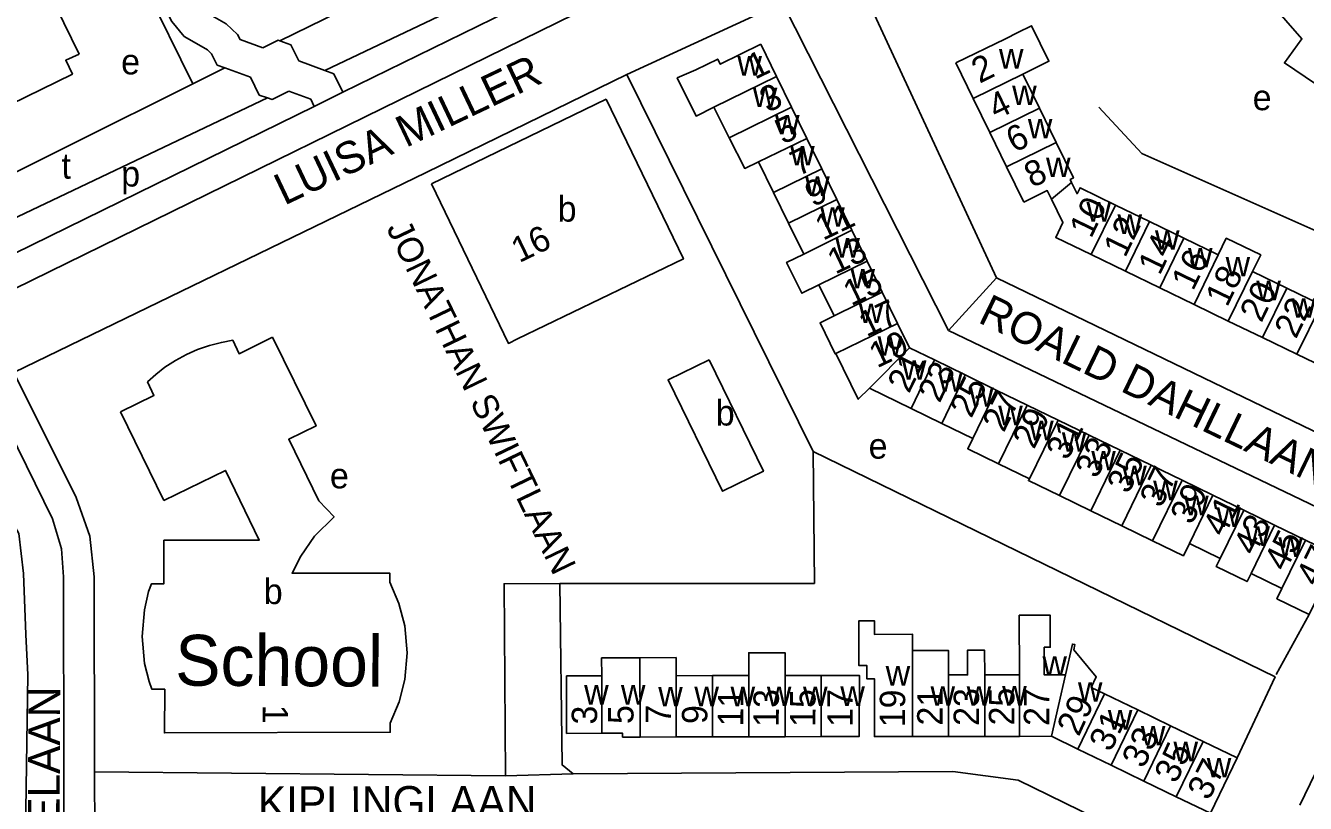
# Model space of a CAD drawing. Extents: x 159441 to 162086, y 388175 to 389787.
# Drawn here: x 161032.2 to 161233.6, y 388694.6 to 388817 of the extents above; entities that cross this region are included whole.
import ezdxf

# ---------------------------------------------------------------- set-up
doc = ezdxf.new("R2010")
doc.units = 0
for name, color, linetype in [('BLT_Basislijn', 7, 'Continuous'), ('BLT_Bebouwing', 7, 'Continuous'), ('BLT_Bebouwing_beschrifting', 7, 'Continuous'), ('BLT_Centroide', 7, 'Continuous'), ('BLT_Huisnummer', 7, 'Continuous'), ('BLT_Huisnummer_ tussenligend', 7, 'Continuous'), ('BLT_Onderverdeling_panden', 7, 'Continuous'), ('BLT_Straatnaam', 7, 'Continuous'), ('BLT_Straatnaam_verkleind', 7, 'Continuous'), ('BLT_Vlakafsluiter', 7, 'Continuous')]:
    doc.layers.add(name, color=color, linetype=linetype)

msp = doc.modelspace()

# ---------------------------------------------------------------- linework, layer by layer
at = {"layer": 'BLT_Basislijn'}
for p, q in [((161216.74, 388872.6), (161082.14, 388806.54)), ((161218.94, 388868.11), (161025.1, 388772.97)), ((161082.14, 388806.54), (161077.65, 388804.33)), ((161077.65, 388804.33), (161025.41, 388778.69)), ((161030.37, 388762.41), (161095.27, 388793.94)), ((161234.25, 388724.34), (161229.06, 388714.88)), ((161032.19, 388688.74), (161032.58, 388714.86))]:
    msp.add_line(p, q, dxfattribs=at)
for points in [[(161036.46, 388739.38), (161017.23, 388778.45), (161001.29, 388811.15), (160975.34, 388864.38), (160962.07, 388891.5)], [(161079.32, 388809.98), (161118.3, 388828.54), (161215.09, 388875.8)], [(161045.71, 388855.38), (161046.68, 388853.81), (161048.97, 388850.86), (161051.97, 388847.76), (161055.4, 388844.7), (161057, 388842.87), (161058.11, 388841.11), (161058.93, 388839.05), (161059.17, 388836.83), (161059, 388834.84), (161058.08, 388829.55), (161058.04, 388827.87), (161058.2, 388826.02), (161058.46, 388822.98), (161058.85, 388821.58), (161059.44, 388820.45), (161060.45, 388819.21), (161062.32, 388818.15), (161063.79, 388817.3), (161065.58, 388815.65), (161065.98, 388814.83), (161069.54, 388813.54)], [(161041.19, 388853.18), (161042.57, 388850.96), (161045.19, 388847.58), (161048.51, 388844.16), (161051.84, 388841.18), (161052.98, 388839.87), (161053.64, 388838.83), (161054.03, 388837.83), (161054.15, 388836.78), (161054.03, 388835.49), (161053.09, 388830.04), (161053.03, 388827.72), (161053.22, 388825.58), (161053.52, 388822.09), (161054.17, 388819.75), (161055.23, 388817.69), (161057.16, 388815.33), (161059.84, 388813.8), (161060.82, 388813.25), (161061.49, 388812.62), (161062.37, 388810.82), (161063.59, 388810.38)], [(161160.76, 388829.76), (161185.03, 388777.32)], [(161058.54, 388807.89), (161051.02, 388823.15)], [(161072.21, 388814.64), (161086.06, 388821.47)], [(161126.83, 388809.34), (161151.36, 388820.64), (161177.47, 388769.07)], [(161069.54, 388813.54), (161071.95, 388814.73), (161072.21, 388814.64)], [(161072.21, 388814.64), (161073.97, 388814.01), (161075.21, 388811.47)], [(161058.54, 388807.89), (161063.59, 388810.38)], [(161063.59, 388810.38), (161067.63, 388808.91)], [(161075.21, 388811.47), (161079.32, 388809.98)], [(161067.63, 388808.91), (161068.99, 388806.1), (161070.26, 388805.67)], [(161079.32, 388809.98), (161080.71, 388809.47), (161082.14, 388806.54)], [(161095.27, 388793.94), (161126.83, 388809.34)], [(161146.87, 388768.8), (161126.83, 388809.34)], [(161020.59, 388788.99), (161058.54, 388807.89)], [(161070.26, 388805.67), (161071.01, 388805.42), (161073.66, 388806.72)], [(161073.66, 388806.72), (161077.1, 388805.47), (161077.65, 388804.33)], [(161023.26, 388783.3), (161070.26, 388805.67)], [(161201.15, 388804.18), (161207.88, 388796.92), (161255.61, 388775.7), (161287.78, 388791.68)], [(161185.03, 388777.32), (161262.68, 388739.84), (161267.15, 388740.53), (161302.57, 388760.98)], [(161116.29, 388729.24), (161156.38, 388729.22), (161156.15, 388750), (161146.87, 388768.8)], [(161177.47, 388769.07), (161262.68, 388728.15), (161263.71, 388725.06), (161239.32, 388674.86), (161236.91, 388674.52)], [(161042.33, 388736.67), (161040.18, 388742.76), (161030.37, 388762.41)], [(161156.15, 388750), (161228.87, 388714.52), (161222.92, 388701.75)], [(161027.09, 388744.3), (161031.14, 388737.08), (161031.88, 388730.79), (161032.25, 388721.17), (161032.58, 388714.86)], [(161038.2, 388730.25), (161037.84, 388734.67), (161036.46, 388739.38)], [(161107.72, 388698.93), (161043.07, 388699.59), (161042.99, 388730.25), (161042.33, 388736.67)], [(161038.25, 388699.64), (161038.2, 388730.25)], [(161116.29, 388729.24), (161107.52, 388729.18), (161107.72, 388698.93)], [(161118.37, 388699.27), (161116.65, 388700.65), (161116.29, 388729.24)], [(161038.68, 388533.55), (161038.25, 388699.64)], [(161236.91, 388674.52), (161188.46, 388698.24), (161178.16, 388699.61), (161118.37, 388699.27)]]:
    msp.add_lwpolyline(points, dxfattribs=at)
at = {"layer": 'BLT_Bebouwing'}
for p, q in [((161147.92, 388814.11), (161150.4, 388809.04)), ((161178.62, 388811.16), (161181.35, 388805.57)), ((161150.4, 388809.04), (161152.77, 388804.21)), ((161191.78, 388804.02), (161189.16, 388809.38)), ((161096.08, 388792.12), (161123.57, 388805.47)), ((161181.35, 388805.57), (161183.96, 388800.2)), ((161152.77, 388804.21), (161155.18, 388799.29)), ((161194.42, 388798.63), (161191.78, 388804.02)), ((161183.96, 388800.2), (161186.61, 388794.81)), ((161155.18, 388799.29), (161157.53, 388794.5)), ((161149.93, 388790.77), (161147.58, 388795.57)), ((161157.53, 388794.5), (161159.91, 388789.65)), ((161186.61, 388794.81), (161189.33, 388789.26)), ((161152.3, 388785.93), (161149.93, 388790.77)), ((161159.91, 388789.65), (161162.27, 388784.82)), ((161209.13, 388786.19), (161203.74, 388788.8)), ((161214.53, 388783.57), (161209.13, 388786.19)), ((161154.68, 388781.08), (161152.3, 388785.93)), ((161162.27, 388784.82), (161164.65, 388779.97)), ((161219.93, 388780.95), (161214.53, 388783.57)), ((161199.92, 388781.01), (161205.34, 388778.39)), ((161164.65, 388779.97), (161167.05, 388775.07)), ((161205.34, 388778.39), (161210.74, 388775.76)), ((161230.73, 388775.72), (161225.33, 388778.33)), ((161159.45, 388771.33), (161157.05, 388776.23)), ((161167.05, 388775.07), (161169.46, 388770.16)), ((161210.74, 388775.76), (161216.14, 388773.15)), ((161236.13, 388773.1), (161230.73, 388775.72)), ((161216.14, 388773.15), (161221.51, 388770.53)), ((161169.46, 388770.16), (161171.35, 388766.3)), ((161221.51, 388770.53), (161226.91, 388767.92)), ((161171.35, 388766.3), (161175.25, 388764.41)), ((161226.91, 388767.92), (161232.31, 388765.31)), ((161175.25, 388764.41), (161180.12, 388762.04)), ((161232.31, 388765.31), (161238.07, 388762.52)), ((161180.12, 388762.04), (161184.99, 388759.67)), ((161171.57, 388756.78), (161165.02, 388759.95)), ((161184.99, 388759.67), (161189.86, 388757.31)), ((161047.14, 388756.25), (161053.97, 388742.29)), ((161176.43, 388754.42), (161171.57, 388756.78)), ((161189.86, 388757.31), (161194.71, 388754.95)), ((161181.29, 388752.06), (161176.43, 388754.42)), ((161194.71, 388754.95), (161199.62, 388752.57)), ((161199.62, 388752.57), (161204.51, 388750.19)), ((161204.51, 388750.19), (161209.37, 388747.83)), ((161190.2, 388745.72), (161185.34, 388748.08)), ((161209.37, 388747.83), (161214.23, 388745.47)), ((161214.23, 388745.47), (161219.08, 388743.11)), ((161199.86, 388740.67), (161194.96, 388743.05)), ((161219.08, 388743.11), (161223.93, 388740.75)), ((161204.73, 388738.3), (161199.86, 388740.67)), ((161223.93, 388740.75), (161228.79, 388738.39)), ((161209.59, 388735.95), (161204.73, 388738.3)), ((161228.79, 388738.39), (161233.64, 388736.03)), ((161220.24, 388733.17), (161215.39, 388735.52)), ((161229.95, 388728.45), (161225.09, 388730.81)), ((161117.35, 388714.67), (161122.89, 388714.68)), ((161117.37, 388705.62), (161117.35, 388714.67)), ((161134.61, 388714.7), (161140.32, 388714.71)), ((161140.32, 388714.71), (161146.07, 388714.72)), ((161151.78, 388714.73), (161157.43, 388714.74)), ((161188.65, 388714.83), (161183.18, 388714.83)), ((161207.28, 388709.32), (161202.02, 388711.86)), ((161212.42, 388706.83), (161207.28, 388709.32)), ((161122.9, 388705.64), (161117.37, 388705.62)), ((161217.55, 388704.35), (161212.42, 388706.83)), ((161134.63, 388705.06), (161128.94, 388705.05)), ((161140.34, 388705.07), (161134.63, 388705.06)), ((161146.04, 388705.08), (161140.34, 388705.07)), ((161151.74, 388705.1), (161146.04, 388705.08)), ((161157.44, 388705.11), (161151.74, 388705.1)), ((161171.79, 388705.12), (161177.49, 388705.13)), ((161177.49, 388705.13), (161183.19, 388705.14)), ((161183.19, 388705.14), (161188.66, 388705.15)), ((161188.66, 388705.15), (161193.67, 388705.16)), ((161193.67, 388705.16), (161197.82, 388703.15)), ((161222.92, 388701.75), (161217.55, 388704.35)), ((161197.82, 388703.15), (161203.08, 388700.61)), ((161203.08, 388700.61), (161208.2, 388698.12)), ((161208.2, 388698.12), (161213.33, 388695.64)), ((161235.19, 388699.3), (161232.79, 388694.35))]:
    msp.add_line(p, q, dxfattribs=at)
for points in [[(161024.55, 388845.47), (161025.4, 388843.76), (161026.83, 388844.47), (161034.9, 388827.99), (161033.46, 388827.27), (161040.64, 388812.57)], [(161237.92, 388811.85), (161235.21, 388807.85), (161230.34, 388811.16), (161233.11, 388814.98), (161228.04, 388820.71)], [(161189.16, 388809.38), (161193.28, 388811.42), (161190.54, 388817.01), (161188.4, 388815.94), (161186.42, 388814.98), (161178.62, 388811.16)], [(161040.64, 388812.57), (161038.53, 388811.58), (161039.59, 388809.41), (161020.01, 388799.84), (161018.93, 388801.99), (161016.82, 388800.96)], [(161140.56, 388804.21), (161137.74, 388802.81), (161134.78, 388808.8), (161137.69, 388810.08), (161141.14, 388811.78), (161141.54, 388810.96), (161147.92, 388814.11)], [(161123.57, 388805.47), (161135.75, 388780.31), (161109.65, 388767.71)], [(161142.93, 388799.37), (161140.56, 388804.21)], [(161147.58, 388795.57), (161145.39, 388794.56), (161142.93, 388799.37)], [(161196.85, 388792.36), (161196.63, 388792.81), (161197.14, 388793.06), (161194.42, 388798.63)], [(161203.74, 388788.8), (161198.17, 388791.51), (161197.72, 388790.58), (161196.85, 388792.36)], [(161109.65, 388767.71), (161108.21, 388767.02), (161096.08, 388792.12)], [(161189.33, 388789.26), (161193.01, 388791.07), (161193.67, 388789.72)], [(161193.67, 388789.72), (161195.48, 388786.02), (161194.35, 388783.71), (161199.92, 388781.01)], [(161225.33, 388778.33), (161226.61, 388780.93), (161221.19, 388783.56), (161219.93, 388780.95)], [(161157.05, 388776.23), (161154.37, 388774.9), (161151.99, 388779.75), (161154.68, 388781.08)], [(161159.75, 388765.41), (161159.65, 388765.36), (161157.25, 388770.25), (161159.45, 388771.33)], [(161071.09, 388767.97), (161065.82, 388765.38), (161064.82, 388767.5), (161063.02, 388767.18), (161061.15, 388766.7), (161059.26, 388766.04), (161057.56, 388765.29), (161055.81, 388764.34), (161054.15, 388763.25), (161052.71, 388762.12), (161051.41, 388760.95), (161052.42, 388758.82), (161047.14, 388756.25)], [(161089.53, 388729.44), (161089.54, 388730.84), (161074.16, 388730.83), (161075.53, 388733.53), (161077.7, 388736.65), (161080.76, 388739.71), (161078.37, 388742.24), (161073.63, 388751.93), (161077.92, 388754.02), (161071.09, 388767.97)], [(161139.79, 388764.43), (161148.34, 388746.88), (161141.89, 388743.74), (161133.34, 388761.29), (161139.79, 388764.43)], [(161165.02, 388759.95), (161163.26, 388758.21), (161159.75, 388765.41)], [(161185.34, 388748.08), (161180.49, 388750.43), (161181.29, 388752.06)], [(161053.97, 388742.29), (161063.65, 388747.03), (161068.98, 388736.04), (161053.97, 388736.02), (161053.97, 388729.18), (161052.03, 388729.18), (161051.58, 388727.96), (161050.91, 388725.07), (161050.57, 388720.86), (161050.94, 388716.65), (161051.64, 388713.77), (161052.09, 388712.58), (161054.11, 388712.56), (161054.07, 388705.71), (161089.6, 388705.79), (161089.59, 388707.21), (161091.01, 388710.57), (161091.9, 388714.11), (161092.27, 388718.32), (161091.9, 388722.53), (161090.98, 388726.08), (161089.53, 388729.44)], [(161194.96, 388743.05), (161190.06, 388745.42), (161190.2, 388745.72)], [(161215.39, 388735.52), (161214.45, 388733.59), (161209.59, 388735.95)], [(161233.64, 388736.03), (161238.73, 388733.56), (161234.25, 388724.34), (161229.15, 388726.81), (161229.95, 388728.45)], [(161225.09, 388730.81), (161224.47, 388729.53), (161219.61, 388731.89), (161220.24, 388733.17)], [(161195.87, 388714.84), (161192.55, 388714.84), (161192.54, 388719.18), (161193.49, 388719.18), (161193.47, 388724.25), (161188.62, 388724.23), (161188.65, 388714.83)], [(161171.81, 388718.67), (161171.81, 388721.23), (161165.85, 388721.18), (161165.84, 388723.32), (161163.34, 388723.32), (161163.35, 388716.32), (161164.61, 388716.32), (161164.6, 388714.23), (161165.82, 388714.23), (161165.82, 388705.11), (161171.79, 388705.12)], [(161202.02, 388711.86), (161199.94, 388712.87), (161200.73, 388714.51), (161197.18, 388718.8), (161197.36, 388719.6), (161196.97, 388719.69), (161195.87, 388714.84)], [(161146.07, 388714.72), (161146.02, 388718.31), (161151.74, 388718.32), (161151.78, 388714.73)], [(161177.48, 388714.82), (161177.46, 388718.69), (161171.81, 388718.67)], [(161183.18, 388714.83), (161183.16, 388718.7), (161180.46, 388718.7), (161180.47, 388714.82), (161177.48, 388714.82)], [(161122.89, 388714.68), (161122.87, 388717.5), (161128.91, 388717.52)], [(161128.91, 388717.52), (161134.6, 388717.55), (161134.61, 388714.7)], [(161157.43, 388714.74), (161163.45, 388714.75), (161163.4, 388705.12), (161157.44, 388705.11)], [(161128.94, 388705.05), (161126.17, 388705.04), (161126.17, 388705.64), (161122.9, 388705.64)], [(161213.33, 388695.64), (161218.7, 388693.04), (161222.92, 388701.75)]]:
    msp.add_lwpolyline(points, dxfattribs=at)
at = {"layer": 'BLT_Onderverdeling_panden'}
for p, q in [((161150.4, 388809.04), (161140.56, 388804.21)), ((161181.35, 388805.57), (161189.16, 388809.38)), ((161152.77, 388804.21), (161142.93, 388799.37)), ((161183.96, 388800.2), (161191.78, 388804.02)), ((161155.18, 388799.29), (161147.58, 388795.57)), ((161186.61, 388794.81), (161194.42, 388798.63)), ((161157.53, 388794.5), (161149.93, 388790.77)), ((161196.85, 388792.36), (161193.67, 388789.72)), ((161159.91, 388789.65), (161152.3, 388785.93)), ((161203.74, 388788.8), (161199.92, 388781.01)), ((161205.34, 388778.39), (161209.13, 388786.19)), ((161162.27, 388784.82), (161154.68, 388781.08)), ((161210.74, 388775.76), (161214.53, 388783.57)), ((161216.14, 388773.15), (161219.93, 388780.95)), ((161164.65, 388779.97), (161157.05, 388776.23)), ((161221.51, 388770.53), (161225.33, 388778.33)), ((161167.05, 388775.07), (161159.45, 388771.33)), ((161226.91, 388767.92), (161230.73, 388775.72)), ((161232.31, 388765.31), (161236.13, 388773.1)), ((161169.46, 388770.16), (161159.75, 388765.41)), ((161171.35, 388766.3), (161165.02, 388759.95)), ((161171.57, 388756.78), (161175.25, 388764.41)), ((161176.43, 388754.42), (161180.12, 388762.04)), ((161181.29, 388752.06), (161184.99, 388759.67)), ((161185.34, 388748.08), (161189.86, 388757.31)), ((161190.2, 388745.72), (161194.71, 388754.95)), ((161194.96, 388743.05), (161199.62, 388752.57)), ((161199.86, 388740.67), (161204.51, 388750.19)), ((161204.73, 388738.3), (161209.37, 388747.83)), ((161209.59, 388735.95), (161214.23, 388745.47)), ((161215.39, 388735.52), (161219.08, 388743.11)), ((161220.24, 388733.17), (161223.93, 388740.75)), ((161225.09, 388730.81), (161228.79, 388738.39)), ((161229.95, 388728.45), (161233.64, 388736.03)), ((161171.79, 388705.12), (161171.81, 388718.67)), ((161128.94, 388705.05), (161128.91, 388717.52)), ((161122.9, 388705.64), (161122.89, 388714.68)), ((161134.63, 388705.06), (161134.61, 388714.7)), ((161140.34, 388705.07), (161140.32, 388714.71)), ((161146.04, 388705.08), (161146.07, 388714.72)), ((161151.74, 388705.1), (161151.78, 388714.73)), ((161157.44, 388705.11), (161157.43, 388714.74)), ((161177.49, 388705.13), (161177.48, 388714.82)), ((161183.19, 388705.14), (161183.18, 388714.83)), ((161188.66, 388705.15), (161188.65, 388714.83)), ((161193.67, 388705.16), (161195.87, 388714.84)), ((161197.82, 388703.15), (161202.02, 388711.86)), ((161203.08, 388700.61), (161207.28, 388709.32)), ((161208.2, 388698.12), (161212.42, 388706.83)), ((161213.33, 388695.64), (161217.55, 388704.35))]:
    msp.add_line(p, q, dxfattribs=at)
at = {"layer": 'BLT_Vlakafsluiter'}
for p, q in [((161177.47, 388769.07), (161185.03, 388777.32)), ((161043.07, 388699.59), (161043.09, 388689.87)), ((161118.37, 388699.27), (161107.72, 388698.93))]:
    msp.add_line(p, q, dxfattribs=at)

# ---------------------------------------------------------------- texts
at = {"layer": 'BLT_Bebouwing_beschrifting'}
msp.add_text('School', height=8, rotation=359.7264, dxfattribs=at).set_placement((161055.74, 388713.15))
at = {"layer": 'BLT_Centroide'}
msp.add_text('e', height=4, rotation=359, dxfattribs=at).set_placement((161047.22, 388809.39))
for s, p in [('w', (161185.41, 388810.28)), ('w', (161144.24, 388809.16)), ('w', (161146.67, 388804.22)), ('w', (161187.49, 388804.52)), ('e', (161225.35, 388803.72)), ('w', (161150.17, 388799.91)), ('w', (161189.96, 388799.29)), ('t', (161037.87, 388792.94)), ('w', (161152.55, 388795.03)), ('w', (161192.82, 388793.19)), ('p', (161047.26, 388791.71)), ('w', (161154.91, 388790.22)), ('b', (161115.95, 388786.19)), ('w', (161157.29, 388785.38)), ('w', (161199.19, 388786.19)), ('w', (161204.07, 388784.24)), ('w', (161209.97, 388781.75)), ('w', (161159.66, 388780.53)), ('w', (161215.17, 388778.98)), ('w', (161221.08, 388777.56)), ('w', (161162.05, 388775.66)), ('w', (161225.92, 388773.8)), ('w', (161231.43, 388771.06)), ('w', (161163.35, 388770.22)), ('w', (161166.31, 388765.06)), ('w', (161170.14, 388761.28)), ('w', (161175.84, 388759.41)), ('w', (161180.72, 388757.05)), ('b', (161140.84, 388754.09)), ('w', (161185.3, 388754.14)), ('w', (161190.16, 388751.78)), ('e', (161164.9, 388748.87)), ('w', (161195.31, 388749.95)), ('w', (161199.94, 388747.03)), ('e', (161080.11, 388744.19)), ('w', (161204.81, 388744.67)), ('w', (161209.69, 388742.31)), ('w', (161214.55, 388739.95)), ('w', (161219.66, 388738.12)), ('w', (161224.2, 388735.14)), ('w', (161229.38, 388733.41)), ('b', (161069.7, 388725.98)), ('w', (161192.25, 388714.7)), ('w', (161167.58, 388713.16)), ('w', (161197.84, 388710.61)), ('w', (161120.12, 388710.16)), ('w', (161125.91, 388710.17)), ('w', (161131.78, 388709.88)), ('w', (161137.47, 388709.89)), ('w', (161143.17, 388709.89)), ('w', (161148.88, 388709.91)), ('w', (161154.58, 388709.91)), ('w', (161160.44, 388709.94)), ('w', (161174.64, 388709.97)), ('w', (161180.33, 388709.97)), ('w', (161185.92, 388710)), ('w', (161202.55, 388706.23)), ('w', (161207.75, 388703.72)), ('w', (161212.88, 388701.23)), ('w', (161218.12, 388698.69))]:
    msp.add_text(s, height=4, dxfattribs=at).set_placement(p)
at = {"layer": 'BLT_Huisnummer'}
for s, rotation, p in [('1', 25.5096, (161147.01, 388808.5)), ('2', 26.0931, (161182.36, 388807.88)), ('5', 25.5096, (161151.41, 388798.28)), ('6', 26.099, (161187.81, 388796.97)), ('9', 25.5096, (161156.12, 388788.43)), ('10', 64.1794, (161199.91, 388783.4)), ('16', 25.7649, (161109.9, 388779.63)), ('14', 64.1796, (161210.71, 388777.59)), ('13', 25.5096, (161159.65, 388777.81)), ('18', 64.183, (161221.32, 388772.6)), ('17', 25.5096, (161164.57, 388767.94)), ('22', 64.1804, (161232.16, 388767.59)), ('21', 64.0791, (161171.26, 388759.02)), ('25', 64.0791, (161181.07, 388755.11)), ('29', 64.0791, (161190.94, 388750.23)), ('33', 64.0791, (161200.83, 388745.59)), ('37', 64.0791, (161210.95, 388740.97)), ('41', 64.0791, (161220.87, 388736.39)), ('47', 64.0791, (161235.57, 388728.57)), ('11', 89.809, (161145.16, 388706.71)), ('17', 89.809, (161162.39, 388706.64)), ('19', 89.809, (161170.64, 388706.57)), ('23', 89.809, (161182.27, 388706.8)), ('27', 89.809, (161193.32, 388706.79)), ('1', 269.809, (161069.54, 388710.15)), ('3', 89.809, (161122.16, 388707.01)), ('7', 89.809, (161133.78, 388707.14)), ('31', 64.357, (161203.01, 388702.55)), ('37', 63.357, (161218.45, 388694.91))]:
    msp.add_text(s, height=4, rotation=rotation, dxfattribs=at).set_placement(p)
at = {"layer": 'BLT_Huisnummer_ tussenligend'}
for s, rotation, p in [('3', 25.5096, (161149, 388803.27)), ('4', 26.0843, (161184.99, 388802.18)), ('7', 25.5096, (161153.81, 388793.28)), ('8', 26.0963, (161190.65, 388791.44)), ('11', 25.5096, (161157.72, 388783.15)), ('12', 64.1794, (161205.27, 388780.37)), ('16', 64.1857, (161215.97, 388775.15)), ('15', 25.5096, (161162.14, 388772.84)), ('20', 64.1861, (161226.72, 388770.15)), ('19', 25.5096, (161166.21, 388763.06)), ('23', 64.0791, (161176.07, 388757.5)), ('27', 64.0791, (161186.18, 388752.86)), ('31', 64.0791, (161196.23, 388748.45)), ('35', 64.0791, (161205.79, 388743.17)), ('39', 64.0791, (161215.77, 388738.31)), ('43', 64.0791, (161225.69, 388733.45)), ('45', 64.0791, (161230.54, 388730.96)), ('13', 89.809, (161150.76, 388706.65)), ('15', 89.809, (161156.53, 388706.64)), ('21', 89.809, (161176.53, 388706.85)), ('25', 89.809, (161187.82, 388706.86)), ('5', 89.809, (161127.89, 388707.09)), ('9', 89.809, (161139.51, 388707.09)), ('29', 65.357, (161197.98, 388705)), ('33', 65.357, (161208.21, 388699.96)), ('35', 65.357, (161213.32, 388697.58))]:
    msp.add_text(s, height=4, rotation=rotation, dxfattribs=at).set_placement(p)
at = {"layer": 'BLT_Straatnaam'}
for s, rotation, p in [('LUISA MILLER', 25.4321, (161072.93, 388788.67)), ('ROALD DAHLLAAN', 334.2283, (161181.93, 388770.41)), ('SHAKESPEARELAAN', 89.712, (161037.33, 388645.72)), ('KIPLINGLAAN', 0.1151, (161068.77, 388692.28))]:
    msp.add_text(s, height=5, rotation=rotation, dxfattribs=at).set_placement(p)
at = {"layer": 'BLT_Straatnaam_verkleind'}
msp.add_text('JONATHAN SWIFTLAAN', height=4, rotation=295.7118, dxfattribs=at).set_placement((161088.95, 388785.16))

doc.saveas('drawing.dxf')
